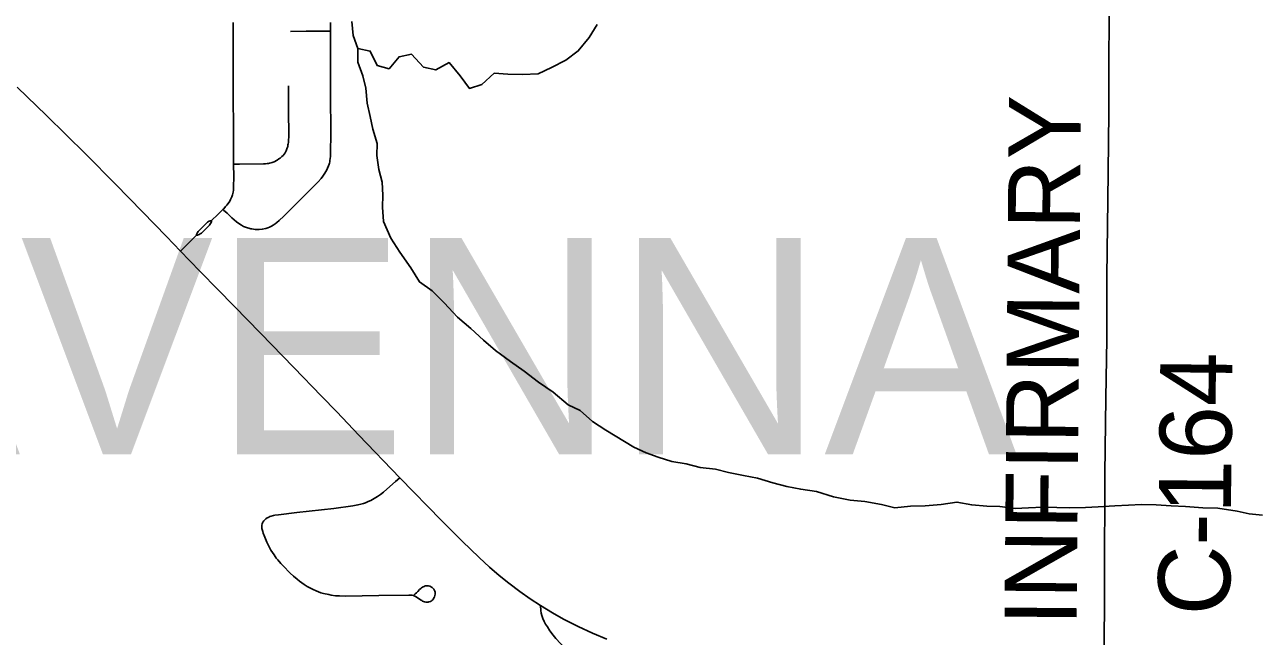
# Model space of a CAD drawing. Extents: x 0 to 34, y 0 to 22.
# Drawn here: x 6.128 to 7.097, y 15.681 to 16.163 of the extents above; entities that cross this region are included whole.
import ezdxf

# ---------------------------------------------------------------- set-up
doc = ezdxf.new("R2010")
doc.units = 0
for name, color, linetype in [('GM_X_County_Road', 7, 'Continuous'), ('GM_X_County_Road_Text', 7, 'Continuous'), ('GM_X_Minor_River', 7, 'Continuous'), ('GM_X_State_Route', 7, 'Continuous'), ('GM_X_Township_Road', 7, 'Continuous'), ('GM_X_Township_Text', 7, 'Continuous')]:
    doc.layers.add(name, color=color, linetype=linetype)

msp = doc.modelspace()

# ---------------------------------------------------------------- linework, layer by layer
at = {"layer": 'GM_X_County_Road'}
for points in [[(6.97861, 15.65986), (6.97897, 15.72591), (6.9793, 15.80935), (6.97989, 15.86905), (6.98067, 15.91545), (6.98089, 15.94538), (6.9808, 15.96462), (6.98158, 16.02481), (6.98188, 16.04709), (6.98225, 16.09397), (6.98237, 16.12529), (6.98252, 16.17571)], [(6.63403, 15.58975), (6.62403, 15.59992), (6.60523, 15.61888), (6.5901, 15.63444), (6.57582, 15.64916), (6.5572, 15.66835), (6.54674, 15.67978), (6.54456, 15.6824), (6.54198, 15.68577), (6.53996, 15.68875), (6.53851, 15.691), (6.53734, 15.69306), (6.53634, 15.69531), (6.53553, 15.69767), (6.53504, 15.6997), (6.53471, 15.70178), (6.53449, 15.70572)]]:
    msp.add_lwpolyline(points, dxfattribs=at)
at = {"layer": 'GM_X_Minor_River'}
for points in [[(6.38579, 16.1656), (6.38701, 16.15461), (6.3905, 16.1444), (6.39059, 16.13341), (6.39446, 16.12282), (6.3968, 16.11299), (6.39803, 16.10124), (6.40039, 16.09064), (6.40236, 16.0808), (6.40586, 16.06945), (6.40555, 16.05997), (6.40715, 16.04899), (6.40988, 16.03915), (6.41034, 16.02892), (6.41004, 16.01944), (6.41089, 16.00807), (6.41667, 15.99485), (6.42357, 15.9839), (6.43237, 15.97146), (6.43927, 15.96052), (6.44917, 15.95339), (6.45871, 15.94398), (6.46901, 15.93269), (6.47968, 15.92367), (6.4896, 15.91465), (6.49912, 15.90638), (6.51093, 15.89775), (6.52158, 15.89025), (6.53301, 15.88162), (6.54442, 15.87374), (6.55624, 15.8636), (6.56573, 15.85912)], [(6.3905, 16.1444), (6.40036, 16.14221), (6.40575, 16.13087), (6.41523, 16.12829), (6.4231, 16.13783), (6.43293, 16.1398), (6.44247, 16.12964), (6.45195, 16.12744), (6.4625, 16.13321), (6.47129, 16.12265), (6.47856, 16.11286), (6.48837, 16.11596), (6.49814, 16.12476), (6.50875, 16.12408), (6.52048, 16.12379), (6.53259, 16.12426), (6.54315, 16.12927), (6.55446, 16.13505), (6.56424, 16.14232), (6.57286, 16.15301), (6.57921, 16.16329)], [(6.56573, 15.85912), (6.57564, 15.85048), (6.58592, 15.84373), (6.60797, 15.83025), (6.61785, 15.82578), (6.62734, 15.82243), (6.63796, 15.81911), (6.64933, 15.8173), (6.66033, 15.81435), (6.67245, 15.81293), (6.68269, 15.81035), (6.69444, 15.80816), (6.70544, 15.80597), (6.71758, 15.80228), (6.72858, 15.79933), (6.73957, 15.79714), (6.75208, 15.79534), (6.76535, 15.79127), (6.77862, 15.78872), (6.78998, 15.78767), (6.80325, 15.78511), (6.81387, 15.78254), (6.82597, 15.78377), (6.8377, 15.78424), (6.85019, 15.78509), (6.86266, 15.78708), (6.87441, 15.7849), (6.88615, 15.78385), (6.89637, 15.78355), (6.90849, 15.78213), (6.91909, 15.78259), (6.93044, 15.78306), (6.94142, 15.78276), (6.95164, 15.78246), (6.96412, 15.78293), (6.97396, 15.78339), (6.9872, 15.78425), (6.9978, 15.78471), (7.00801, 15.78517), (7.01975, 15.78488), (7.03148, 15.78421), (7.04284, 15.78354), (7.05648, 15.7825), (7.06821, 15.78222), (7.08337, 15.78006), (7.09285, 15.77786), (7.10345, 15.7768)]]:
    msp.add_lwpolyline(points, dxfattribs=at)
at = {"layer": 'GM_X_State_Route'}
for points in [[(6.12228, 16.11376), (6.14527, 16.09164), (6.17623, 16.06118), (6.1996, 16.03739), (6.22079, 16.01566), (6.23989, 15.99624), (6.25095, 15.98472), (6.25797, 15.9774), (6.26662, 15.96848), (6.28012, 15.95474), (6.29311, 15.94135), (6.31379, 15.92014), (6.34024, 15.89314), (6.36208, 15.87051), (6.37399, 15.85808)], [(6.37399, 15.85808), (6.39149, 15.83979), (6.42373, 15.80612), (6.45649, 15.77252), (6.47282, 15.75635), (6.48625, 15.74343), (6.49444, 15.73585), (6.50194, 15.72936), (6.50965, 15.72315), (6.51822, 15.71677), (6.52636, 15.71101), (6.53449, 15.70572), (6.54403, 15.69981), (6.55267, 15.69496), (6.56422, 15.68901), (6.57546, 15.68379), (6.58691, 15.67906)]]:
    msp.add_lwpolyline(points, dxfattribs=at)
at = {"layer": 'GM_X_Township_Road'}
for points in [[(6.29272, 16.05322), (6.29258, 16.07715), (6.29235, 16.11073), (6.29227, 16.16485)], [(6.36899, 16.1648), (6.36912, 16.15797)], [(6.36912, 16.15797), (6.36917, 16.1477), (6.36913, 16.10303), (6.36923, 16.08251), (6.36925, 16.07335), (6.36917, 16.06595), (6.36909, 16.06214), (6.36903, 16.06035), (6.36896, 16.0592), (6.36883, 16.05775), (6.3686, 16.05596), (6.36841, 16.05505), (6.36817, 16.05401), (6.36793, 16.0531), (6.36757, 16.05197), (6.36678, 16.04994), (6.36625, 16.04886), (6.3646, 16.04604), (6.363, 16.04375), (6.36164, 16.04201), (6.35923, 16.03928), (6.35708, 16.037), (6.33227, 16.01215), (6.32862, 16.0088), (6.32688, 16.00734), (6.32546, 16.00628), (6.32381, 16.00517), (6.32262, 16.00445), (6.32106, 16.00366), (6.31958, 16.00307), (6.31819, 16.00263), (6.31523, 16.00193), (6.31287, 16.00175), (6.31098, 16.00175), (6.30981, 16.00184), (6.30837, 16.00202), (6.30708, 16.0022), (6.30621, 16.00234), (6.30465, 16.00269), (6.30354, 16.003), (6.30201, 16.00353), (6.30056, 16.0042), (6.29882, 16.00513), (6.29679, 16.00649), (6.29507, 16.00778), (6.2914, 16.01096), (6.28755, 16.01455), (6.28483, 16.01709)], [(6.33747, 16.15758), (6.35001, 16.15783), (6.36499, 16.15794), (6.36912, 16.15797)], [(6.29272, 16.05322), (6.29747, 16.05327), (6.31632, 16.05345), (6.31796, 16.05351), (6.31903, 16.05361), (6.3203, 16.05378), (6.32096, 16.05391), (6.32207, 16.05417), (6.32314, 16.05451), (6.32462, 16.05514), (6.32716, 16.05648), (6.32846, 16.05732), (6.32939, 16.05801), (6.33073, 16.05917), (6.33167, 16.06014), (6.33242, 16.06106), (6.33322, 16.06219), (6.33401, 16.06362), (6.3344, 16.06442), (6.33477, 16.06538), (6.33515, 16.06655), (6.33534, 16.06723), (6.33557, 16.0683), (6.33573, 16.06922), (6.33586, 16.07016), (6.33596, 16.07141), (6.33605, 16.0726), (6.33611, 16.07413), (6.33614, 16.07523), (6.33616, 16.07694), (6.33616, 16.07995), (6.33599, 16.09131), (6.336, 16.11481)], [(6.28433, 16.01756), (6.28488, 16.01811), (6.28641, 16.01977), (6.28744, 16.02099), (6.28846, 16.02228), (6.28966, 16.02407), (6.29036, 16.0253), (6.29125, 16.02738), (6.2918, 16.02904), (6.29231, 16.03121), (6.29251, 16.03261), (6.29268, 16.03518), (6.29276, 16.04354), (6.29272, 16.05322)], [(6.26344, 15.99717), (6.26432, 15.99734), (6.26562, 15.9978), (6.26649, 15.9983), (6.26736, 15.99899), (6.27181, 16.00333), (6.2736, 16.00523), (6.27408, 16.00573), (6.27456, 16.00636), (6.27504, 16.00726), (6.27525, 16.00814), (6.27529, 16.00883), (6.2804, 16.01365), (6.28433, 16.01756)], [(6.26344, 15.99717), (6.26354, 15.99785), (6.26369, 15.99845), (6.26418, 15.99947), (6.26473, 16.00021), (6.27225, 16.00761), (6.27283, 16.00806), (6.27337, 16.00838), (6.27415, 16.00868), (6.27529, 16.00883)], [(6.25095, 15.98472), (6.25332, 15.98709), (6.26344, 15.99717)], [(6.31577, 15.77134), (6.31653, 15.77239), (6.31732, 15.77325), (6.31808, 15.77393), (6.31907, 15.77462), (6.31984, 15.77505), (6.3204, 15.77534), (6.32114, 15.77566), (6.32237, 15.77602), (6.32424, 15.7765), (6.32529, 15.77673), (6.32805, 15.77713), (6.34266, 15.77884), (6.37169, 15.78199), (6.38661, 15.78402), (6.39066, 15.78482), (6.39287, 15.78536), (6.39516, 15.7861), (6.39656, 15.78663), (6.39868, 15.78752), (6.40073, 15.78844), (6.40346, 15.78989), (6.40612, 15.79149), (6.40835, 15.79299), (6.41074, 15.79481), (6.41355, 15.79716), (6.4204, 15.8032), (6.42373, 15.80612)], [(6.31577, 15.77134), (6.31546, 15.77068), (6.31517, 15.76988), (6.31495, 15.76883), (6.3149, 15.76767), (6.31503, 15.76636), (6.31523, 15.76544), (6.31565, 15.764), (6.31613, 15.76251), (6.31734, 15.75936), (6.31894, 15.75549), (6.32034, 15.7525), (6.32215, 15.74915), (6.32326, 15.74738), (6.32455, 15.74546), (6.32636, 15.74297), (6.32744, 15.74158), (6.32985, 15.73877), (6.33169, 15.73681), (6.33739, 15.73118), (6.33999, 15.72876), (6.34275, 15.72634), (6.34474, 15.72478), (6.34826, 15.72229), (6.35073, 15.72073), (6.35277, 15.7195), (6.35539, 15.71819), (6.35781, 15.71712), (6.36156, 15.71576), (6.36358, 15.71514), (6.36763, 15.7142), (6.36956, 15.71385), (6.37313, 15.7134), (6.37609, 15.71319), (6.38089, 15.71311), (6.40707, 15.71363), (6.4308, 15.71392), (6.43202, 15.71385), (6.43336, 15.7137), (6.43446, 15.71344), (6.43551, 15.71304), (6.43656, 15.71244), (6.44007, 15.71), (6.44091, 15.70947), (6.44165, 15.70906), (6.44227, 15.7088), (6.44314, 15.70852), (6.44416, 15.70832), (6.44478, 15.70826), (6.44593, 15.70833), (6.44659, 15.70847), (6.44777, 15.70887), (6.44834, 15.70917), (6.44903, 15.70966), (6.44967, 15.71024), (6.45007, 15.71075), (6.45076, 15.71183), (6.45108, 15.71258), (6.45139, 15.71366), (6.45153, 15.71449), (6.45152, 15.71528), (6.45147, 15.71609), (6.45126, 15.71692), (6.45101, 15.71756), (6.45049, 15.71844), (6.44976, 15.71925), (6.44921, 15.71977), (6.4486, 15.72022), (6.44796, 15.7206), (6.44728, 15.72086), (6.44624, 15.72113), (6.44557, 15.72121), (6.44459, 15.72122), (6.44369, 15.72104), (6.44283, 15.72071), (6.44217, 15.7204), (6.44156, 15.72004), (6.44089, 15.71957), (6.44031, 15.71911), (6.4393, 15.71815), (6.43783, 15.71669), (6.43695, 15.71573), (6.43589, 15.71472), (6.43499, 15.71397)]]:
    msp.add_lwpolyline(points, dxfattribs=at)

# ---------------------------------------------------------------- texts
at = {"layer": 'GM_X_County_Road_Text'}
for s, rotation, p in [('INFIRMARY', 89.51393, (6.95694, 15.68946)), ('C-164', 89.45718, (7.07781, 15.69778))]:
    msp.add_text(s, height=0.056818, rotation=rotation, dxfattribs=at).set_placement(p)
at = {"layer": 'GM_X_Township_Text'}
msp.add_text('RAVENNA', height=0.170455, rotation=0.00001, dxfattribs=at).set_placement((5.80814, 15.8246))

doc.saveas('drawing.dxf')
